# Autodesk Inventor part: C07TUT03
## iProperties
Created: 2009-04
Part Number: C07TUT03
Document SubType Name: Modeling
Designer: Sham
Density: 1 g/cm^3
Author: Sham
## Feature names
1. Extrusion1
2. Extrusion2
3. Extrusion3
4. Hole1
5. Hole2
6. Circular Pattern1
7. Extrusion4
8. Circular Pattern2
9. Mirror1
